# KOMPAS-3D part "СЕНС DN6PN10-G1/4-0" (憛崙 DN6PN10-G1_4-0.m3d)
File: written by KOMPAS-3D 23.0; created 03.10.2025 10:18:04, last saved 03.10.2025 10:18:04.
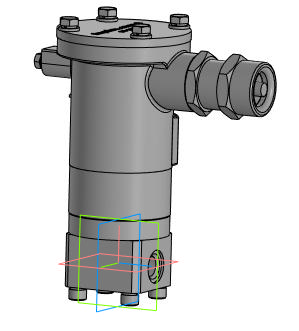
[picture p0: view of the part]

Document properties: Автор: setup; Полное имя файла: D:\WS127\D\Савин\!СЕНСОР\3D для заказчика\!Новый перечень\СЕНС\11. СЕНС-G(K)\СЕНС DN6PN10-G1_4-0.m3d

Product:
- Part/product: СЕНС DN6PN10-G1/4-0
    Масса: 2.085524

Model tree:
1. Операция без истории:1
